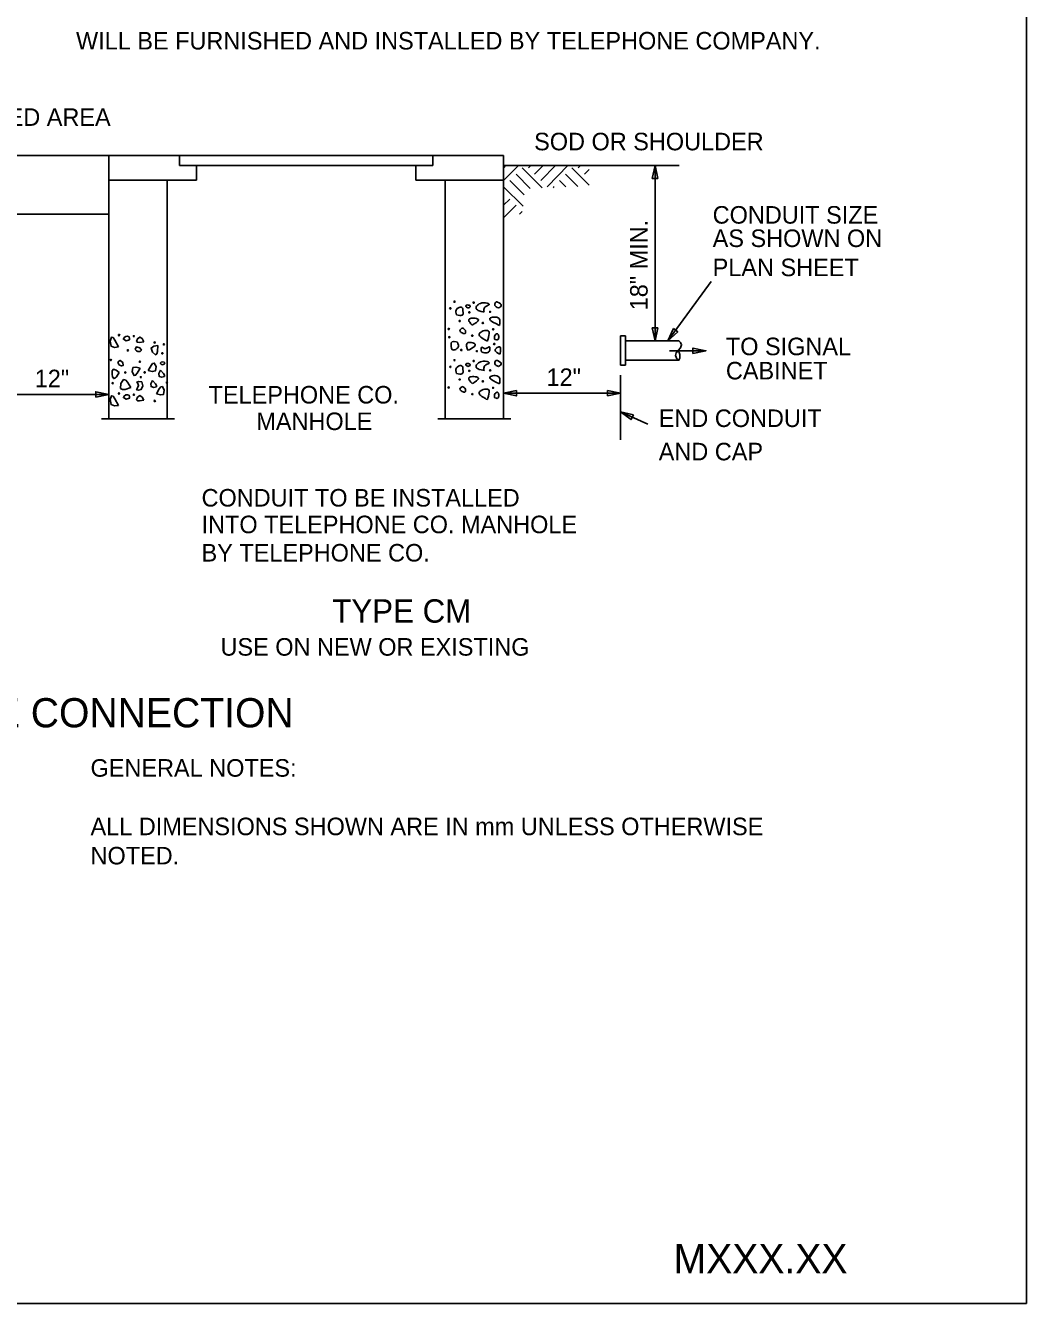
# Model space of a CAD drawing. Extents: x -439.1 to -407.9, y -458.1 to -436.2.
# Drawn here: x -416.41 to -407.86, y -458.05 to -447.12 of the extents above; entities that cross this region are included whole.
import ezdxf

# ---------------------------------------------------------------- set-up
doc = ezdxf.new("R2010")
doc.units = 0
for name, color, linetype in [('Draft_Named_Boundary', 7, 'Continuous'), ('Level 4', 7, 'Continuous'), ('Level 46', 7, 'Continuous')]:
    doc.layers.add(name, color=color, linetype=linetype)

msp = doc.modelspace()

# ---------------------------------------------------------------- linework, layer by layer
at = {"layer": 'Draft_Named_Boundary'}
msp.add_lwpolyline([(-439.109, -458.051), (-407.859, -458.051), (-407.859, -437.676), (-439.109, -437.676)], close=True, dxfattribs=at)
at = {"layer": 'Level 4'}
for p, q in [((-417.224, -448.236), (-412.328, -448.236)), ((-415.703, -448.236), (-415.703, -450.486)), ((-415.099, -448.236), (-415.099, -448.32)), ((-412.933, -448.236), (-412.933, -448.32)), ((-412.328, -450.486), (-412.328, -448.236)), ((-415.099, -448.32), (-412.933, -448.32)), ((-414.953, -448.32), (-414.953, -448.445)), ((-413.078, -448.32), (-413.078, -448.445)), ((-412.329, -448.449), (-412.199, -448.319)), ((-412.329, -448.343), (-412.305, -448.319)), ((-410.828, -448.32), (-412.328, -448.32)), ((-412.101, -448.517), (-412.222, -448.395)), ((-411.999, -448.512), (-412.169, -448.342)), ((-412.116, -448.342), (-412.093, -448.319)), ((-412.063, -448.395), (-411.987, -448.319)), ((-412.01, -448.449), (-411.881, -448.319)), ((-411.957, -448.502), (-411.775, -448.319)), ((-411.693, -448.5), (-411.798, -448.395)), ((-411.597, -448.49), (-411.745, -448.342)), ((-411.692, -448.342), (-411.668, -448.319)), ((-411.638, -448.395), (-411.597, -448.354)), ((-411.034, -448.32), (-411.034, -449.819)), ((-415.703, -448.445), (-414.953, -448.445)), ((-415.203, -448.445), (-415.203, -450.486)), ((-413.078, -448.445), (-412.328, -448.445)), ((-412.828, -448.445), (-412.828, -450.486)), ((-412.16, -448.669), (-412.328, -448.502)), ((-412.153, -448.571), (-412.275, -448.449)), ((-411.897, -448.508), (-411.904, -448.502)), ((-411.795, -448.504), (-411.851, -448.449)), ((-412.329, -448.555), (-412.328, -448.555)), ((-412.329, -448.661), (-412.275, -448.608)), ((-417.224, -448.736), (-415.703, -448.736)), ((-412.329, -448.768), (-412.222, -448.661)), ((-412.193, -448.738), (-412.169, -448.714)), ((-410.924, -449.819), (-410.554, -449.313)), ((-412.325, -449.466), (-412.325, -449.466)), ((-411.328, -450.028), (-411.328, -449.778)), ((-411.287, -449.778), (-411.328, -449.778)), ((-411.287, -450.028), (-411.287, -449.778)), ((-410.828, -449.819), (-411.287, -449.819)), ((-410.91, -449.905), (-410.599, -449.905)), ((-412.325, -449.966), (-412.325, -449.966)), ((-412.325, -449.966), (-412.325, -449.966)), ((-411.287, -450.028), (-411.328, -450.028)), ((-410.828, -449.986), (-411.287, -449.986)), ((-411.329, -450.115), (-411.329, -450.666)), ((-416.704, -450.279), (-415.703, -450.279)), ((-412.328, -450.268), (-411.329, -450.268)), ((-415.766, -450.486), (-415.141, -450.486)), ((-412.891, -450.486), (-412.266, -450.486)), ((-411.329, -450.427), (-411.095, -450.534))]:
    msp.add_line(p, q, dxfattribs=at)
for points in [[(-411.011, -448.431), (-411.034, -448.32), (-411.057, -448.431)], [(-412.635, -449.539), (-412.628, -449.537), (-412.621, -449.534), (-412.615, -449.53), (-412.614, -449.528), (-412.613, -449.526), (-412.614, -449.522), (-412.617, -449.519), (-412.622, -449.516), (-412.628, -449.514), (-412.636, -449.513), (-412.644, -449.514), (-412.649, -449.517), (-412.651, -449.519), (-412.652, -449.521), (-412.652, -449.524), (-412.65, -449.527), (-412.646, -449.531), (-412.635, -449.539)], [(-412.495, -449.573), (-412.505, -449.572), (-412.521, -449.568), (-412.536, -449.564), (-412.546, -449.56), (-412.552, -449.556), (-412.559, -449.55), (-412.562, -449.547), (-412.563, -449.543), (-412.564, -449.537), (-412.563, -449.532), (-412.559, -449.524), (-412.552, -449.516), (-412.544, -449.509), (-412.538, -449.505), (-412.526, -449.5), (-412.513, -449.496), (-412.502, -449.495), (-412.485, -449.495), (-412.469, -449.498), (-412.461, -449.501), (-412.456, -449.503), (-412.453, -449.505), (-412.451, -449.508), (-412.451, -449.51), (-412.453, -449.513), (-412.46, -449.516), (-412.468, -449.52), (-412.48, -449.526), (-412.485, -449.53), (-412.49, -449.534), (-412.493, -449.538), (-412.495, -449.545), (-412.497, -449.553), (-412.496, -449.563), (-412.495, -449.573)], [(-412.372, -449.539), (-412.363, -449.534), (-412.355, -449.528), (-412.349, -449.521), (-412.348, -449.517), (-412.348, -449.514), (-412.35, -449.509), (-412.354, -449.505), (-412.366, -449.496), (-412.379, -449.489), (-412.385, -449.487), (-412.39, -449.487), (-412.393, -449.488), (-412.397, -449.492), (-412.4, -449.497), (-412.402, -449.505), (-412.403, -449.512), (-412.402, -449.518), (-412.397, -449.524), (-412.392, -449.53), (-412.382, -449.535), (-412.372, -449.539)], [(-412.73, -449.599), (-412.716, -449.602), (-412.701, -449.604), (-412.694, -449.604), (-412.685, -449.602), (-412.681, -449.6), (-412.678, -449.597), (-412.676, -449.594), (-412.675, -449.589), (-412.674, -449.582), (-412.676, -449.562), (-412.678, -449.546), (-412.68, -449.54), (-412.684, -449.535), (-412.688, -449.533), (-412.693, -449.532), (-412.7, -449.532), (-412.708, -449.534), (-412.715, -449.537), (-412.724, -449.544), (-412.732, -449.552), (-412.734, -449.557), (-412.737, -449.566), (-412.737, -449.575), (-412.734, -449.587), (-412.73, -449.599)], [(-412.363, -449.689), (-412.36, -449.673), (-412.359, -449.655), (-412.36, -449.647), (-412.361, -449.641), (-412.365, -449.633), (-412.37, -449.627), (-412.379, -449.622), (-412.386, -449.619), (-412.399, -449.617), (-412.412, -449.617), (-412.423, -449.619), (-412.431, -449.621), (-412.44, -449.624), (-412.444, -449.627), (-412.446, -449.629), (-412.447, -449.632), (-412.447, -449.635), (-412.444, -449.641), (-412.44, -449.645), (-412.431, -449.652), (-412.42, -449.66), (-412.39, -449.676), (-412.376, -449.683), (-412.363, -449.689)], [(-412.684, -449.711), (-412.695, -449.721), (-412.699, -449.726), (-412.701, -449.732), (-412.7, -449.738), (-412.697, -449.742), (-412.691, -449.748), (-412.683, -449.753), (-412.675, -449.757), (-412.67, -449.758), (-412.662, -449.759), (-412.659, -449.758), (-412.657, -449.756), (-412.655, -449.754), (-412.653, -449.749), (-412.653, -449.742), (-412.655, -449.733), (-412.66, -449.725), (-412.665, -449.72), (-412.671, -449.716), (-412.677, -449.713), (-412.684, -449.711)], [(-412.597, -449.686), (-412.607, -449.674), (-412.618, -449.661), (-412.622, -449.654), (-412.624, -449.65), (-412.626, -449.643), (-412.624, -449.637), (-412.622, -449.634), (-412.619, -449.632), (-412.612, -449.629), (-412.606, -449.627), (-412.595, -449.626), (-412.584, -449.626), (-412.57, -449.627), (-412.561, -449.629), (-412.555, -449.631), (-412.548, -449.635), (-412.546, -449.637), (-412.544, -449.639), (-412.544, -449.642), (-412.545, -449.647), (-412.547, -449.651), (-412.553, -449.657), (-412.561, -449.663), (-412.579, -449.676), (-412.589, -449.681), (-412.597, -449.686)], [(-412.467, -449.822), (-412.463, -449.811), (-412.457, -449.792), (-412.453, -449.773), (-412.451, -449.761), (-412.451, -449.752), (-412.452, -449.747), (-412.455, -449.74), (-412.461, -449.735), (-412.465, -449.733), (-412.473, -449.732), (-412.48, -449.732), (-412.491, -449.733), (-412.502, -449.736), (-412.514, -449.741), (-412.521, -449.746), (-412.53, -449.753), (-412.533, -449.757), (-412.536, -449.761), (-412.536, -449.765), (-412.536, -449.769), (-412.534, -449.776), (-412.53, -449.781), (-412.523, -449.788), (-412.515, -449.795), (-412.503, -449.803), (-412.484, -449.813), (-412.476, -449.818), (-412.467, -449.822)], [(-411.057, -449.709), (-411.034, -449.819), (-411.011, -449.709)], [(-410.877, -449.716), (-410.924, -449.819), (-410.84, -449.744)], [(-415.621, -449.872), (-415.654, -449.876), (-415.683, -449.865), (-415.692, -449.823), (-415.681, -449.789), (-415.666, -449.793), (-415.65, -449.815), (-415.621, -449.872)], [(-415.529, -449.785), (-415.525, -449.799), (-415.527, -449.811), (-415.554, -449.819), (-415.578, -449.806), (-415.572, -449.793), (-415.557, -449.782), (-415.543, -449.781), (-415.529, -449.785)], [(-415.404, -449.828), (-415.441, -449.834), (-415.457, -449.832), (-415.466, -449.825), (-415.458, -449.803), (-415.439, -449.788), (-415.418, -449.801), (-415.404, -449.828)], [(-412.721, -449.832), (-412.735, -449.828), (-412.75, -449.826), (-412.757, -449.827), (-412.767, -449.829), (-412.77, -449.831), (-412.773, -449.833), (-412.775, -449.836), (-412.777, -449.842), (-412.777, -449.849), (-412.775, -449.869), (-412.773, -449.884), (-412.771, -449.89), (-412.768, -449.895), (-412.763, -449.898), (-412.759, -449.899), (-412.752, -449.898), (-412.744, -449.896), (-412.737, -449.893), (-412.727, -449.887), (-412.72, -449.879), (-412.717, -449.874), (-412.715, -449.865), (-412.715, -449.856), (-412.718, -449.843), (-412.721, -449.832)], [(-412.633, -449.901), (-412.639, -449.885), (-412.644, -449.867), (-412.645, -449.859), (-412.645, -449.853), (-412.643, -449.845), (-412.641, -449.842), (-412.639, -449.839), (-412.632, -449.835), (-412.625, -449.834), (-412.614, -449.833), (-412.602, -449.835), (-412.591, -449.837), (-412.585, -449.84), (-412.576, -449.844), (-412.573, -449.847), (-412.571, -449.85), (-412.57, -449.853), (-412.572, -449.859), (-412.574, -449.863), (-412.581, -449.87), (-412.59, -449.877), (-412.612, -449.89), (-412.623, -449.896), (-412.633, -449.901)], [(-412.403, -449.808), (-412.389, -449.811), (-412.382, -449.812), (-412.377, -449.81), (-412.373, -449.805), (-412.371, -449.8), (-412.369, -449.792), (-412.369, -449.782), (-412.371, -449.774), (-412.373, -449.769), (-412.377, -449.762), (-412.379, -449.76), (-412.382, -449.759), (-412.385, -449.759), (-412.39, -449.761), (-412.395, -449.764), (-412.401, -449.771), (-412.405, -449.779), (-412.407, -449.787), (-412.407, -449.794), (-412.405, -449.801), (-412.403, -449.808)], [(-415.477, -449.895), (-415.473, -449.881), (-415.465, -449.871), (-415.438, -449.879), (-415.424, -449.901), (-415.436, -449.91), (-415.454, -449.911), (-415.467, -449.905), (-415.477, -449.895)], [(-415.284, -449.861), (-415.318, -449.866), (-415.342, -449.882), (-415.33, -449.918), (-415.303, -449.939), (-415.293, -449.93), (-415.287, -449.91), (-415.284, -449.861)], [(-412.517, -449.915), (-412.519, -449.904), (-412.52, -449.891), (-412.519, -449.885), (-412.518, -449.878), (-412.516, -449.876), (-412.515, -449.875), (-412.512, -449.875), (-412.508, -449.877), (-412.503, -449.881), (-412.495, -449.885), (-412.491, -449.887), (-412.486, -449.888), (-412.481, -449.887), (-412.473, -449.884), (-412.465, -449.879), (-412.457, -449.873), (-412.453, -449.871), (-412.45, -449.871), (-412.448, -449.873), (-412.446, -449.875), (-412.445, -449.881), (-412.445, -449.887), (-412.447, -449.9), (-412.449, -449.907), (-412.452, -449.912), (-412.458, -449.918), (-412.463, -449.921), (-412.472, -449.924), (-412.482, -449.924), (-412.491, -449.923), (-412.504, -449.919), (-412.517, -449.915)], [(-412.36, -449.933), (-412.358, -449.925), (-412.356, -449.91), (-412.354, -449.896), (-412.354, -449.887), (-412.355, -449.881), (-412.356, -449.877), (-412.359, -449.873), (-412.363, -449.871), (-412.368, -449.871), (-412.376, -449.873), (-412.385, -449.878), (-412.39, -449.883), (-412.397, -449.89), (-412.399, -449.894), (-412.4, -449.898), (-412.4, -449.904), (-412.398, -449.908), (-412.393, -449.913), (-412.387, -449.919), (-412.373, -449.927), (-412.36, -449.933)], [(-410.71, -449.928), (-410.599, -449.905), (-410.71, -449.882)], [(-415.625, -450.004), (-415.616, -449.993), (-415.605, -449.987), (-415.583, -450.005), (-415.58, -450.031), (-415.594, -450.035), (-415.611, -450.028), (-415.621, -450.017), (-415.625, -450.004)], [(-415.436, -450.055), (-415.469, -450.044), (-415.497, -450.049), (-415.502, -450.086), (-415.487, -450.117), (-415.474, -450.114), (-415.46, -450.098), (-415.436, -450.055)], [(-415.365, -450.073), (-415.332, -450.083), (-415.304, -450.078), (-415.299, -450.041), (-415.315, -450.011), (-415.328, -450.014), (-415.341, -450.03), (-415.365, -450.073)], [(-415.243, -450.026), (-415.23, -450.019), (-415.224, -450.009), (-415.229, -450.003), (-415.241, -450), (-415.256, -450.003), (-415.263, -450.011), (-415.256, -450.02), (-415.243, -450.026)], [(-412.73, -450.099), (-412.716, -450.102), (-412.701, -450.104), (-412.694, -450.104), (-412.685, -450.102), (-412.681, -450.1), (-412.678, -450.097), (-412.676, -450.094), (-412.675, -450.089), (-412.674, -450.082), (-412.676, -450.062), (-412.678, -450.046), (-412.68, -450.04), (-412.684, -450.035), (-412.688, -450.033), (-412.693, -450.032), (-412.7, -450.032), (-412.708, -450.034), (-412.715, -450.037), (-412.724, -450.044), (-412.732, -450.052), (-412.734, -450.057), (-412.737, -450.066), (-412.737, -450.075), (-412.734, -450.087), (-412.73, -450.099)], [(-412.635, -450.039), (-412.628, -450.037), (-412.621, -450.034), (-412.615, -450.03), (-412.614, -450.028), (-412.613, -450.026), (-412.614, -450.022), (-412.617, -450.019), (-412.622, -450.016), (-412.628, -450.014), (-412.636, -450.013), (-412.644, -450.014), (-412.649, -450.017), (-412.651, -450.019), (-412.652, -450.021), (-412.652, -450.024), (-412.65, -450.027), (-412.646, -450.031), (-412.635, -450.039)], [(-412.495, -450.073), (-412.505, -450.072), (-412.521, -450.068), (-412.536, -450.064), (-412.546, -450.06), (-412.552, -450.056), (-412.559, -450.05), (-412.562, -450.047), (-412.563, -450.043), (-412.564, -450.037), (-412.563, -450.032), (-412.559, -450.024), (-412.552, -450.016), (-412.544, -450.009), (-412.538, -450.005), (-412.526, -450), (-412.513, -449.996), (-412.502, -449.995), (-412.485, -449.995), (-412.469, -449.998), (-412.461, -450.001), (-412.456, -450.003), (-412.453, -450.005), (-412.451, -450.008), (-412.451, -450.01), (-412.453, -450.013), (-412.46, -450.016), (-412.468, -450.02), (-412.48, -450.026), (-412.485, -450.03), (-412.49, -450.034), (-412.493, -450.038), (-412.495, -450.045), (-412.497, -450.053), (-412.496, -450.063), (-412.495, -450.073)], [(-412.372, -450.039), (-412.363, -450.034), (-412.355, -450.028), (-412.349, -450.021), (-412.348, -450.017), (-412.348, -450.014), (-412.35, -450.009), (-412.354, -450.005), (-412.366, -449.996), (-412.379, -449.989), (-412.385, -449.987), (-412.39, -449.987), (-412.393, -449.988), (-412.397, -449.992), (-412.4, -449.997), (-412.402, -450.005), (-412.403, -450.012), (-412.402, -450.018), (-412.397, -450.024), (-412.392, -450.03), (-412.382, -450.035), (-412.372, -450.039)], [(-415.614, -450.091), (-415.64, -450.07), (-415.663, -450.063), (-415.673, -450.078), (-415.675, -450.104), (-415.67, -450.129), (-415.661, -450.143), (-415.65, -450.14), (-415.638, -450.127), (-415.614, -450.091)], [(-415.514, -450.22), (-415.564, -450.235), (-415.587, -450.236), (-415.602, -450.227), (-415.6, -450.185), (-415.576, -450.152), (-415.558, -450.156), (-415.542, -450.173), (-415.514, -450.22)], [(-415.421, -450.171), (-415.446, -450.168), (-415.462, -450.173), (-415.456, -450.185), (-415.449, -450.202), (-415.458, -450.223), (-415.466, -450.238), (-415.449, -450.243), (-415.425, -450.236), (-415.413, -450.206), (-415.421, -450.171)], [(-415.329, -450.16), (-415.303, -450.187), (-415.294, -450.202), (-415.296, -450.213), (-415.318, -450.219), (-415.342, -450.212), (-415.343, -450.187), (-415.329, -450.16)], [(-415.26, -450.072), (-415.234, -450.099), (-415.226, -450.113), (-415.227, -450.125), (-415.25, -450.131), (-415.273, -450.124), (-415.274, -450.099), (-415.26, -450.072)], [(-412.597, -450.186), (-412.607, -450.174), (-412.618, -450.161), (-412.622, -450.154), (-412.624, -450.15), (-412.626, -450.143), (-412.624, -450.137), (-412.622, -450.134), (-412.619, -450.132), (-412.612, -450.129), (-412.606, -450.127), (-412.595, -450.126), (-412.584, -450.126), (-412.57, -450.127), (-412.561, -450.129), (-412.555, -450.131), (-412.548, -450.135), (-412.546, -450.137), (-412.544, -450.139), (-412.544, -450.142), (-412.545, -450.147), (-412.547, -450.151), (-412.553, -450.157), (-412.561, -450.163), (-412.579, -450.176), (-412.589, -450.181), (-412.597, -450.186)], [(-412.363, -450.189), (-412.36, -450.173), (-412.359, -450.155), (-412.36, -450.147), (-412.361, -450.141), (-412.365, -450.133), (-412.37, -450.127), (-412.379, -450.122), (-412.386, -450.119), (-412.399, -450.117), (-412.412, -450.117), (-412.423, -450.119), (-412.431, -450.121), (-412.44, -450.124), (-412.444, -450.127), (-412.446, -450.129), (-412.447, -450.132), (-412.447, -450.135), (-412.444, -450.141), (-412.44, -450.145), (-412.431, -450.152), (-412.42, -450.16), (-412.39, -450.176), (-412.376, -450.183), (-412.363, -450.189)], [(-415.814, -450.302), (-415.703, -450.279), (-415.814, -450.256)], [(-415.295, -450.273), (-415.262, -450.283), (-415.234, -450.278), (-415.229, -450.241), (-415.244, -450.211), (-415.258, -450.214), (-415.271, -450.23), (-415.295, -450.273)], [(-412.684, -450.211), (-412.695, -450.221), (-412.699, -450.226), (-412.701, -450.232), (-412.7, -450.238), (-412.697, -450.242), (-412.691, -450.248), (-412.683, -450.253), (-412.675, -450.257), (-412.67, -450.258), (-412.662, -450.259), (-412.659, -450.258), (-412.657, -450.256), (-412.655, -450.254), (-412.653, -450.249), (-412.653, -450.242), (-412.655, -450.233), (-412.66, -450.225), (-412.665, -450.22), (-412.671, -450.216), (-412.677, -450.213), (-412.684, -450.211)], [(-412.467, -450.322), (-412.463, -450.311), (-412.457, -450.292), (-412.453, -450.273), (-412.451, -450.261), (-412.451, -450.252), (-412.452, -450.247), (-412.455, -450.24), (-412.461, -450.235), (-412.465, -450.233), (-412.473, -450.232), (-412.48, -450.232), (-412.491, -450.233), (-412.502, -450.236), (-412.514, -450.241), (-412.521, -450.246), (-412.53, -450.253), (-412.533, -450.257), (-412.536, -450.261), (-412.536, -450.265), (-412.536, -450.269), (-412.534, -450.276), (-412.53, -450.281), (-412.523, -450.288), (-412.515, -450.295), (-412.503, -450.303), (-412.484, -450.313), (-412.476, -450.318), (-412.467, -450.322)], [(-412.403, -450.308), (-412.389, -450.311), (-412.382, -450.312), (-412.377, -450.31), (-412.373, -450.305), (-412.371, -450.3), (-412.369, -450.292), (-412.369, -450.282), (-412.371, -450.274), (-412.373, -450.269), (-412.377, -450.262), (-412.379, -450.26), (-412.382, -450.259), (-412.385, -450.259), (-412.39, -450.261), (-412.395, -450.264), (-412.401, -450.271), (-412.405, -450.279), (-412.407, -450.287), (-412.407, -450.294), (-412.405, -450.301), (-412.403, -450.308)], [(-412.218, -450.245), (-412.328, -450.268), (-412.218, -450.291)], [(-411.439, -450.291), (-411.329, -450.268), (-411.439, -450.245)], [(-415.621, -450.372), (-415.654, -450.376), (-415.683, -450.365), (-415.692, -450.323), (-415.681, -450.289), (-415.666, -450.293), (-415.65, -450.315), (-415.621, -450.372)], [(-415.529, -450.285), (-415.525, -450.299), (-415.527, -450.311), (-415.554, -450.319), (-415.578, -450.306), (-415.572, -450.293), (-415.557, -450.282), (-415.543, -450.281), (-415.529, -450.285)], [(-415.404, -450.328), (-415.441, -450.334), (-415.457, -450.332), (-415.466, -450.325), (-415.458, -450.303), (-415.439, -450.288), (-415.418, -450.301), (-415.404, -450.328)], [(-411.219, -450.452), (-411.329, -450.427), (-411.238, -450.494)]]:
    msp.add_lwpolyline(points, close=True, dxfattribs=at)
msp.add_lwpolyline([(-410.829, -449.819), (-410.815, -449.835), (-410.807, -449.853), (-410.816, -449.879), (-410.837, -449.904), (-410.853, -449.923), (-410.858, -449.946), (-410.846, -449.974), (-410.829, -449.986), (-410.821, -449.968), (-410.822, -449.938), (-410.828, -449.919), (-410.837, -449.904)], dxfattribs=at)
for centre, start, end in [((-412.748, -449.486), 0, 180), ((-412.748, -449.486), 180, 0), ((-412.584, -449.493), 90, 270), ((-412.584, -449.493), 270, 90), ((-412.784, -449.543), 0, 180), ((-412.784, -449.543), 180, 0), ((-412.621, -449.577), 90, 270), ((-412.621, -449.577), 270, 90), ((-412.443, -449.572), 90, 270), ((-412.443, -449.572), 270, 90), ((-412.797, -449.719), 0, 180), ((-412.797, -449.719), 180, 0), ((-412.704, -449.651), 90, 270), ((-412.704, -449.651), 270, 90), ((-412.506, -449.667), 90, 270), ((-412.506, -449.667), 270, 90), ((-412.417, -449.722), 90, 270), ((-412.417, -449.722), 270, 90), ((-415.615, -449.771), 0, 180), ((-415.615, -449.771), 180, 0), ((-415.489, -449.78), 0, 180), ((-415.489, -449.78), 180, 0), ((-415.31, -449.834), 0, 180), ((-415.31, -449.834), 180, 0), ((-412.792, -449.789), 0, 180), ((-412.792, -449.789), 180, 0), ((-412.596, -449.776), 90, 270), ((-412.596, -449.776), 270, 90), ((-412.408, -449.847), 90, 270), ((-412.408, -449.847), 270, 90), ((-415.54, -449.902), 0, 180), ((-415.54, -449.902), 180, 0), ((-415.245, -449.927), 0, 180), ((-415.245, -449.927), 180, 0), ((-415.233, -449.85), 0, 180), ((-415.233, -449.85), 180, 0), ((-412.69, -449.899), 90, 270), ((-412.69, -449.899), 270, 90), ((-412.557, -449.908), 90, 270), ((-412.557, -449.908), 270, 90), ((-415.685, -449.984), 0, 180), ((-415.685, -449.984), 180, 0), ((-415.438, -449.998), 0, 180), ((-415.438, -449.998), 180, 0), ((-412.784, -450.043), 0, 180), ((-412.784, -450.043), 180, 0), ((-412.748, -449.986), 0, 180), ((-412.748, -449.986), 180, 0), ((-412.584, -449.993), 90, 270), ((-412.584, -449.993), 270, 90), ((-415.561, -450.091), 0, 180), ((-415.561, -450.091), 180, 0), ((-415.429, -450.131), 0, 180), ((-415.429, -450.131), 180, 0), ((-415.396, -450.09), 0, 180), ((-415.396, -450.09), 180, 0), ((-412.704, -450.151), 90, 270), ((-412.704, -450.151), 270, 90), ((-412.621, -450.077), 90, 270), ((-412.621, -450.077), 270, 90), ((-412.506, -450.167), 90, 270), ((-412.506, -450.167), 270, 90), ((-412.443, -450.072), 90, 270), ((-412.443, -450.072), 270, 90), ((-415.67, -450.182), 0, 180), ((-415.67, -450.182), 180, 0), ((-415.615, -450.271), 0, 180), ((-415.615, -450.271), 180, 0), ((-415.489, -450.28), 0, 180), ((-415.207, -450.178), 0, 180), ((-415.207, -450.178), 180, 0), ((-412.797, -450.219), 0, 180), ((-412.797, -450.219), 180, 0), ((-412.596, -450.276), 90, 270), ((-412.596, -450.276), 270, 90), ((-412.417, -450.222), 90, 270), ((-412.417, -450.222), 270, 90), ((-415.489, -450.28), 180, 0), ((-415.31, -450.334), 0, 180), ((-415.31, -450.334), 180, 0)]:
    msp.add_arc(centre, 0.00521, start, end, dxfattribs=at)

# ---------------------------------------------------------------- texts
for s, height, p in [('WILL BE FURNISHED AND INSTALLED BY TELEPHONE COMPANY.', 0.15, (-415.983, -447.329)), ('PAVED AREA', 0.15, (-416.969, -447.982)), ('SOD OR SHOULDER', 0.15, (-412.067, -448.191)), ('CONDUIT SIZE', 0.15, (-410.541, -448.818)), ('AS SHOWN ON', 0.15, (-410.541, -449.018)), ('PLAN SHEET', 0.15, (-410.541, -449.267)), ('TO SIGNAL', 0.15, (-410.428, -449.943)), ('12"', 0.15, (-411.961, -450.206)), ('CABINET', 0.15, (-410.428, -450.15)), ('12"', 0.15, (-416.336, -450.217)), ('TELEPHONE CO.', 0.15, (-414.85, -450.356)), ('MANHOLE', 0.15, (-414.442, -450.583)), ('END CONDUIT', 0.15, (-411.002, -450.557)), ('AND CAP', 0.15, (-411.002, -450.842)), ('CONDUIT TO BE INSTALLED', 0.15, (-414.91, -451.237)), ('INTO TELEPHONE CO. MANHOLE', 0.15, (-414.91, -451.465)), ('BY TELEPHONE CO.', 0.15, (-414.91, -451.707)), ('TYPE CM', 0.2, (-413.793, -452.23)), ('USE ON NEW OR EXISTING', 0.15, (-414.748, -452.512)), ('UNDERGROUND TELEPHONE CONNECTION', 0.25, (-421.255, -453.125))]:
    msp.add_text(s, height=height, dxfattribs=at).set_placement(p)
msp.add_text('18" MIN.', height=0.15, rotation=90, dxfattribs=at).set_placement((-411.097, -449.559))
at = {"layer": 'Level 46'}
for s, height, p in [('GENERAL NOTES:', 0.15, (-415.859, -453.547)), ('ALL DIMENSIONS SHOWN ARE IN mm UNLESS OTHERWISE ', 0.15, (-415.859, -454.047)), ('NOTED.', 0.15, (-415.859, -454.297)), ('MXXX.XX', 0.25, (-410.875, -457.792))]:
    msp.add_text(s, height=height, dxfattribs=at).set_placement(p)

doc.saveas('drawing.dxf')
